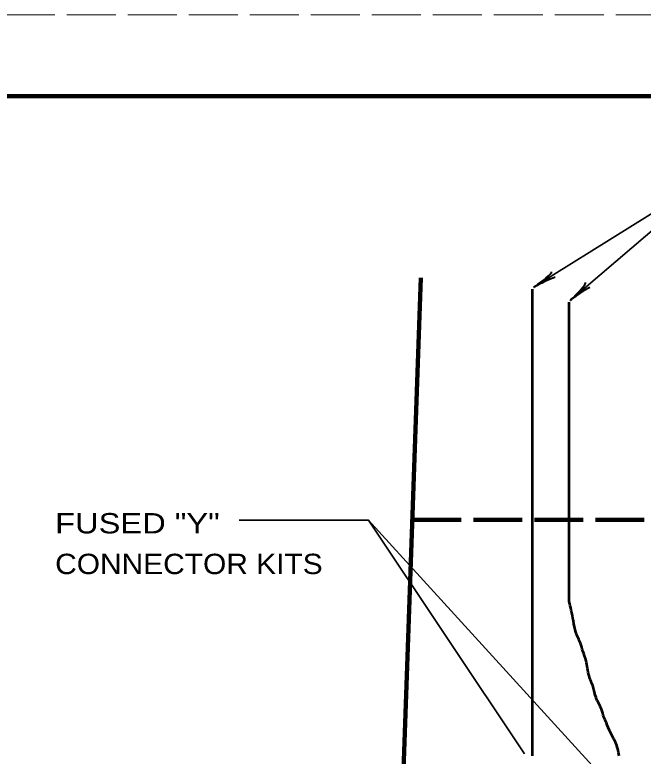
# Model space of a CAD drawing. Extents: x -153 to 527, y -247 to 194.
# Drawn here: x 43 to 120.3, y 102.4 to 193.5 of the extents above; entities that cross this region are included whole.
import ezdxf

# ---------------------------------------------------------------- set-up
doc = ezdxf.new("R2010")
doc.units = 0
doc.linetypes.add('LONG_DASHED', pattern=[7.5, 6, -1.5])
doc.layers.add('1', color=7, linetype='Continuous', lineweight=53)
doc.layers.add('61', color=7, linetype='Continuous', lineweight=35)

msp = doc.modelspace()

# ---------------------------------------------------------------- linework, layer by layer
at = {"layer": '1', "lineweight": 35}
for p, q in [((130.479, 174.774), (111.31, 158.406)), ((86.516, 131.404), (70.607, 131.404)), ((86.516, 131.404), (105.701, 102.663)), ((86.516, 131.404), (114.867, 100.269))]:
    msp.add_line(p, q, dxfattribs=at)
at = {"layer": '1', "lineweight": 90}
msp.add_line((90.13, 80.231), (92.956, 161.182), dxfattribs=at)
at = {"layer": '1'}
for p, q in [((106.686, 102.434), (106.686, 159.789)), ((111.186, 121.384), (111.186, 158.185))]:
    msp.add_line(p, q, dxfattribs=at)
at = {"layer": '1', "linetype": 'LONG_DASHED', "lineweight": 90}
msp.add_line((91.917, 131.427), (134.65, 131.427), dxfattribs=at)
at = {"layer": '1', "lineweight": 35}
msp.add_lwpolyline([(134.277, 174.774), (130.479, 174.774), (106.81, 160.01)], dxfattribs=at)
at = {"layer": '1', "lineweight": 40}
for centre, major_axis, ratio, start_param, end_param in [((107.589, 160.822), (-1.433, -1.078), 0.122415, 0.896353, 3.141593), ((107.589, 160.822), (-1.433, -1.078), 0.122415, 0.896353, 3.141593), ((107.872, 160.424), (1.583, 0.781), 0.07063, 6.282307, 8.559703), ((107.872, 160.424), (1.583, 0.781), 0.07063, 6.282307, 8.559703), ((111.96, 159.325), (-1.257, -1.278), 0.122415, 0.896353, 3.141593), ((111.96, 159.325), (-1.257, -1.278), 0.122415, 0.896353, 3.141593), ((112.299, 158.973), (1.45, 1.007), 0.07063, 6.282307, 8.559703), ((112.299, 158.973), (1.45, 1.007), 0.07063, 6.282307, 8.559703)]:
    msp.add_ellipse(centre, major_axis=major_axis, ratio=ratio, start_param=start_param, end_param=end_param, dxfattribs=at)
at = {"layer": '1'}
msp.add_spline([(117.345, 102.409), (116.888, 104.084), (116.228, 105.353), (115.771, 106.47), (115.467, 107.18), (115.162, 108.145), (114.502, 109.566), (114.147, 110.886), (113.639, 112.256), (113.284, 114.083), (112.878, 115.301), (112.574, 116.266), (112.015, 117.586), (111.711, 119.007), (111.457, 120.326), (111.186, 121.384)], degree=3, dxfattribs=at)
at = {"layer": '61', "linetype": 'LONG_DASHED', "lineweight": 13}
msp.add_line((-153.062, 193.509), (526.958, 193.509), dxfattribs=at)
at = {"layer": '61', "lineweight": 158}
msp.add_lwpolyline([(515.978, 183.509), (-123.062, 183.509), (-123.062, -236.511)], dxfattribs=at)

# ---------------------------------------------------------------- texts
at = {"layer": '1'}
for s, width, p in [('FUSED "Y"', 1.2, (47.994, 129.757)), ('CONNECTOR KITS', 1.1, (47.994, 124.757))]:
    msp.add_text(s, height=2.5, dxfattribs=dict(at, width=width)).set_placement(p)

doc.saveas('drawing.dxf')
